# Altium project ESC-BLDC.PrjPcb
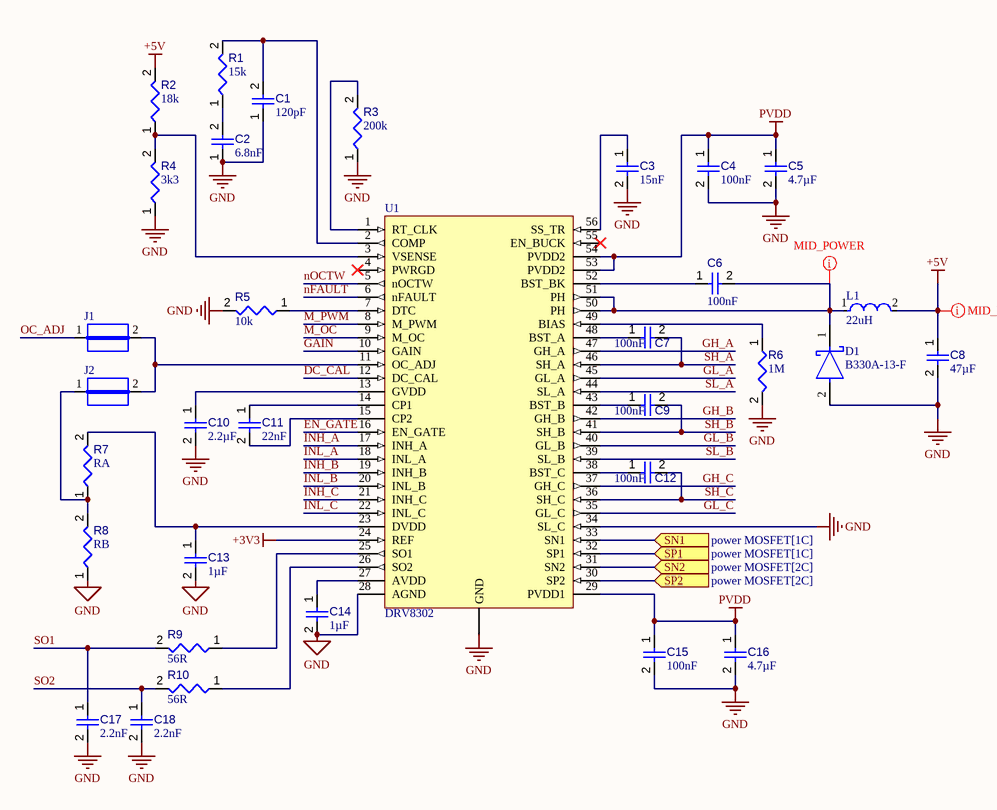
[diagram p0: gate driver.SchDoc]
5 sheets, 131 parts. Net scope: global (net labels, ports and power ports of the same name join across sheets).
Board file: BLDC_ESC.PcbDoc
Sheets:
  gate driver.SchDoc
  power MOSFET.SchDoc
  rotor angle sensor.SchDoc
  CAN.SchDoc
  main controller.SchDoc

## Sheet gate driver.SchDoc
size A4; SheetNumber: 1; SheetTotal: 5

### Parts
C1  value 120pF  [CAPC1005X56X25NL10T15]  (hidden comment: Capacitor 6.8 nF +/- 10% 16 V 0402)
C2  value 6.8nF  [CAPC1005X56X25NL10T15]  (hidden comment: Capacitor 6.8 nF +/- 10% 16 V 0402)
C3  value 15nF  [CAPC0402(1005)60_L]  (hidden comment: Capacitor 22nF +/-20% 10V 0402)
C4  value 100nF  [CAPC1608X90X40NL10T20]  (hidden comment: Capacitor 100 nF +/-10% 50 V 0603)
C5  value 4.7µF  [CAPC0603(1608)100_L]  (hidden comment: Capacitor 4.7µF +/-20% 10V 0603)
C6  value 100nF  [CAPC1608X90X40NL10T20]  (hidden comment: Capacitor 100 nF +/-10% 50 V 0603)
C7  value 100nF  [CAPC1608X90X40NL10T20]  (hidden comment: Capacitor 100 nF +/-10% 50 V 0603)
C8  value 47µF  [CAPC0805(2012)145_L]  (hidden comment: Capacitor 47µF +/-40% 6.3V 0805)
C9  value 100nF  [CAPC1608X90X40NL10T20]  (hidden comment: Capacitor 100 nF +/-10% 50 V 0603)
C10  value 2.2µF  [CAPC0402(1005)60_L]  (hidden comment: Capacitor 2,2µF +/-20% 10V 0402)
C11  value 22nF  [CAPC0402(1005)60_L]  (hidden comment: Capacitor 22nF +/-20% 10V 0402)
C12  value 100nF  [CAPC1608X90X40NL10T20]  (hidden comment: Capacitor 100 nF +/-10% 50 V 0603)
C13  value 1µF  [CAPC0402(1005)60_L]  (hidden comment: Capacitor 1µF +/-20% 10V 0402)
C14  value 1µF  [CAPC0402(1005)60_L]  (hidden comment: Capacitor 1µF +/-20% 10V 0402)
C15  value 100nF  [CAPC1608X90X40NL10T20]  (hidden comment: Capacitor 100 nF +/-10% 50 V 0603)
C16  value 4.7µF  [CAPC0603(1608)100_L]  (hidden comment: Capacitor 4.7µF +/-20% 10V 0603)
C17  value 2.2nF  [CAPC0402(1005)60_L]  (hidden comment: Capacitor 22nF +/-20% 10V 0402)
C18  value 2.2nF  [CAPC0402(1005)60_L]  (hidden comment: Capacitor 22nF +/-20% 10V 0402)
D1  B330A-13-F  [FP-SMA-MFG]
J1  JUMPER  [JUMPER]  (value not drawn)
J2  JUMPER  [JUMPER]  (value not drawn)
L1  22uH  [FP-IHLP-2525CZ-FP_2_413x3-MFG]
R1  value 15k  [RESC1005X40X25ML10T10]  (hidden comment: Resistor 15k +/-1% 0402 63 mW)
R2  value 18k  [RESC1608X55X25ML10T15]  (hidden comment: Resistor 10k +/-1% 0603 100 mW)
R3  value 200k  [RESC0402(1005)_L]  (hidden comment: Resistor 200K +/-1 % 0402 63 mW)
R4  value 3k3  [RESC1608X55X25ML10T15]  (hidden comment: Resistor 10k +/-1% 0603 100 mW)
R5  value 10k  [RESC1005X40X25ML05T05]  (hidden comment: Resistor 10k +/-1% 0402 100 mW)
R6  value 1M  [RESC1608X55X25ML10T15]  (hidden comment: Resistor 10k +/-1% 0603 100 mW)
R7  value RA  [RESC1608X55X25ML10T15]  (hidden comment: Resistor 10k +/-1% 0603 100 mW)
R8  value RB  [RESC1608X55X25ML10T15]  (hidden comment: Resistor 10k +/-1% 0603 100 mW)
R9  value 56R  [RESC1005X40X25ML05T05]  (hidden comment: Resistor 10k +/-1% 0402 100 mW)
R10  value 56R  [RESC1005X40X25ML05T05]  (hidden comment: Resistor 10k +/-1% 0402 100 mW)
U1  DRV8302  [HTSSOP-56]

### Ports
SN1 (in, see power MOSFET[1C]), SN2 (in, see power MOSFET[2C]), SP1 (in, see power MOSFET[1C]), SP2 (in, see power MOSFET[2C])

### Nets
+3V3: U1.24(REF)
+5V: C8.1 L1.2 R2.2
GND: C1.1 C2.1 C3.2 C4.2 C5.2 C8.2 C10.2 C13.2 C14.2 C15.2 C16.2 C17.2 C18.2 D1.2(A) R3.1 R4.1 R5.2 R6.2 R8.1 U1.28(AGND) U1.30(SP2) U1.32(SP1) U1.34(SL_C) U1.EXP(GND) ; port SP1, port SP2
PVDD: C4.1 C5.1 C15.1 C16.1 U1.29(PVDD1) U1.53(PVDD2) U1.54(PVDD2)
DC_CAL: U1.12(DC_CAL)
EN_GATE: U1.16(EN_GATE)
GAIN: U1.10(GAIN)
GH_A: U1.47(GH_A)
GH_B: U1.42(GH_B)
GH_C: U1.37(GH_C)
GL_A: U1.45(GL_A)
GL_B: U1.40(GL_B)
GL_C: U1.35(GL_C)
INH_A: U1.17(INH_A)
INH_B: U1.19(INH_B)
INH_C: U1.21(INH_C)
INL_A: U1.18(INL_A)
INL_B: U1.20(INL_B)
INL_C: U1.22(INL_C)
M_OC: U1.9(M_OC)
M_PWM: U1.8(M_PWM)
nFAULT: U1.6(nFAULT)
nOCTW: U1.5(nOCTW)
OC_ADJ: J1.1
SH_A: C7.2 U1.46(SH_A)
SH_B: C9.2 U1.41(SH_B)
SH_C: C12.2 U1.36(SH_C)
SL_A: U1.33(SN1) U1.44(SL_A) ; port SN1
SL_B: U1.31(SN2) U1.39(SL_B) ; port SN2
SO1: C17.1 R9.2
SO2: C18.1 R10.2
NetC1_2: C1.2 R1.2 U1.2(COMP)
NetC2_2: C2.2 R1.1
NetC3_1: C3.1 U1.56(SS_TR)
NetC6_1: C6.1 U1.52(BST_BK)
NetC6_2: C6.2 D1.1(C) L1.1 U1.50(PH) U1.51(PH)
NetC7_1: C7.1 U1.48(BST_A)
NetC9_1: C9.1 U1.43(BST_B)
NetC10_1: C10.1 U1.13(GVDD)
NetC11_1: C11.1 U1.14(CP1)
NetC11_2: C11.2 U1.15(CP2)
NetC12_1: C12.1 U1.38(BST_C)
NetC13_1: C13.1 R7.2 U1.23(DVDD)
NetC14_1: C14.1 U1.27(AVDD)
NetJ1_2: J1.2 J2.2 U1.11(OC_ADJ)
NetJ2_1: J2.1 R7.1 R8.2
NetR2_1: R2.1 R4.2 U1.3(VSENSE)
NetR3_2: R3.2 U1.1(RT_CLK)
NetR5_1: R5.1 U1.7(DTC)
NetR6_1: R6.1 U1.49(BIAS)
NetR9_1: R9.1 U1.25(SO1)
NetR10_1: R10.1 U1.26(SO2)

Not connected (* = marked no-connect by the designer): U1 4(PWRGD)* 55(EN_BUCK)*

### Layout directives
net class MID_POWER: +5V, NetC6_2

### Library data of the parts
C1 C2 = CMP-001-00000-6: Chip Capacitor, 6.8 nF, +/- 10%, 16 V, 0402 (1005 Metric); Capacitor Type: Ceramic; Voltage Rating: 16V
C3 C11 C17 C18 = CMP-001-00062-3: Chip Capacitor, 22nF +/-20%, 10V, 0402, Thickness 0.6 mm; Tolerance: 10%
C4 C6 C7 C9 C12 C15 = CMP-001-00017-6: Chip Capacitor, 100 nF, +/- 10%, 50 V, 0603 (1608 Metric); Voltage Rating: 50V; Capacitor Type: Ceramic
C5 C16 = CMP-001-00076-4: Chip Capacitor, 4.7µF +/-20%, 10V, 0603, Thickness 1 mm; Tolerance: 10%
C8 = CMP-001-00082-4: Chip Capacitor, 47µF +/-40%, 6.3V, 0805, Thickness 1.45 mm; Tolerance: 10%
C10 = CMP-001-00056-4: Chip Capacitor, 2,2µF +/-20%, 10V, 0402, Thickness 0.6 mm; Tolerance: 10%
C13 C14 = CMP-001-00063-3: Chip Capacitor, 1µF +/-20%, 10V, 0402, Thickness 0.6 mm; Tolerance: 10%
D1 = CMP-2000-05896-2: DIODE SCHOTTKY 30V 3A SMA; Manufacturer: Diodes; Max Junction Temp: +150°C; Standoff Height: 0.05mm; Peak Reverse Current: 0.5mA; Capacitance: 200pF; Value: 200pF; Description: Diode Schottky 30V 3A Surface Mount SMA; Max Surge Forward Current: 80A; Automotive Grade: Grade 0
J1 J2 = CMP-009-00061-2
L1 = CMP-2000-06442-2: Commercial Inductors, Low DCR Series 22uH 2.9A 135mΩ 20%; Self Resonant Frequency: 1MHz; Shielding: Shielded; Core Material: Ferrite; DC Resistance (DCR): 135mR; Test Frequency: 100kHz; Saturation Current: 2.5A
R1 = CMP-009-00026-5: Chip Resistor, 15 KOhm, +/- 1%, 0.063 W, -55 to 155 degC, 0402 (1005 Metric); Power: 63mW
R2 R4 R6-R8 = CMP-009-00017-5: Chip Resistor, 10 KOhm, +/- 1%, 01 W, -55 to 155 degC, 0603 (1608 Metric); Voltage Rating: 50V; Power: 100mW
R3 = CMP-009-00163-3: Chip Resistor, 200 kOhms, +/-1 %, 63 mW, -55 to 155 degC, 0402; Power: 63mW; Tolerance: 1%
R5 R9 R10 = CMP-009-00015-5: Chip Resistor, 10 KOhm, +/- 1%, 0.1 W, -55 to 155 degC, 0402 (1005 Metric); Voltage Rating: 50V; Power: 100mW
U1 = DRV8302: Three phases gate driver with dual current shunt amplifiers and buck regulator

## Sheet power MOSFET.SchDoc
size A4; SheetNumber: 2; SheetTotal: 5
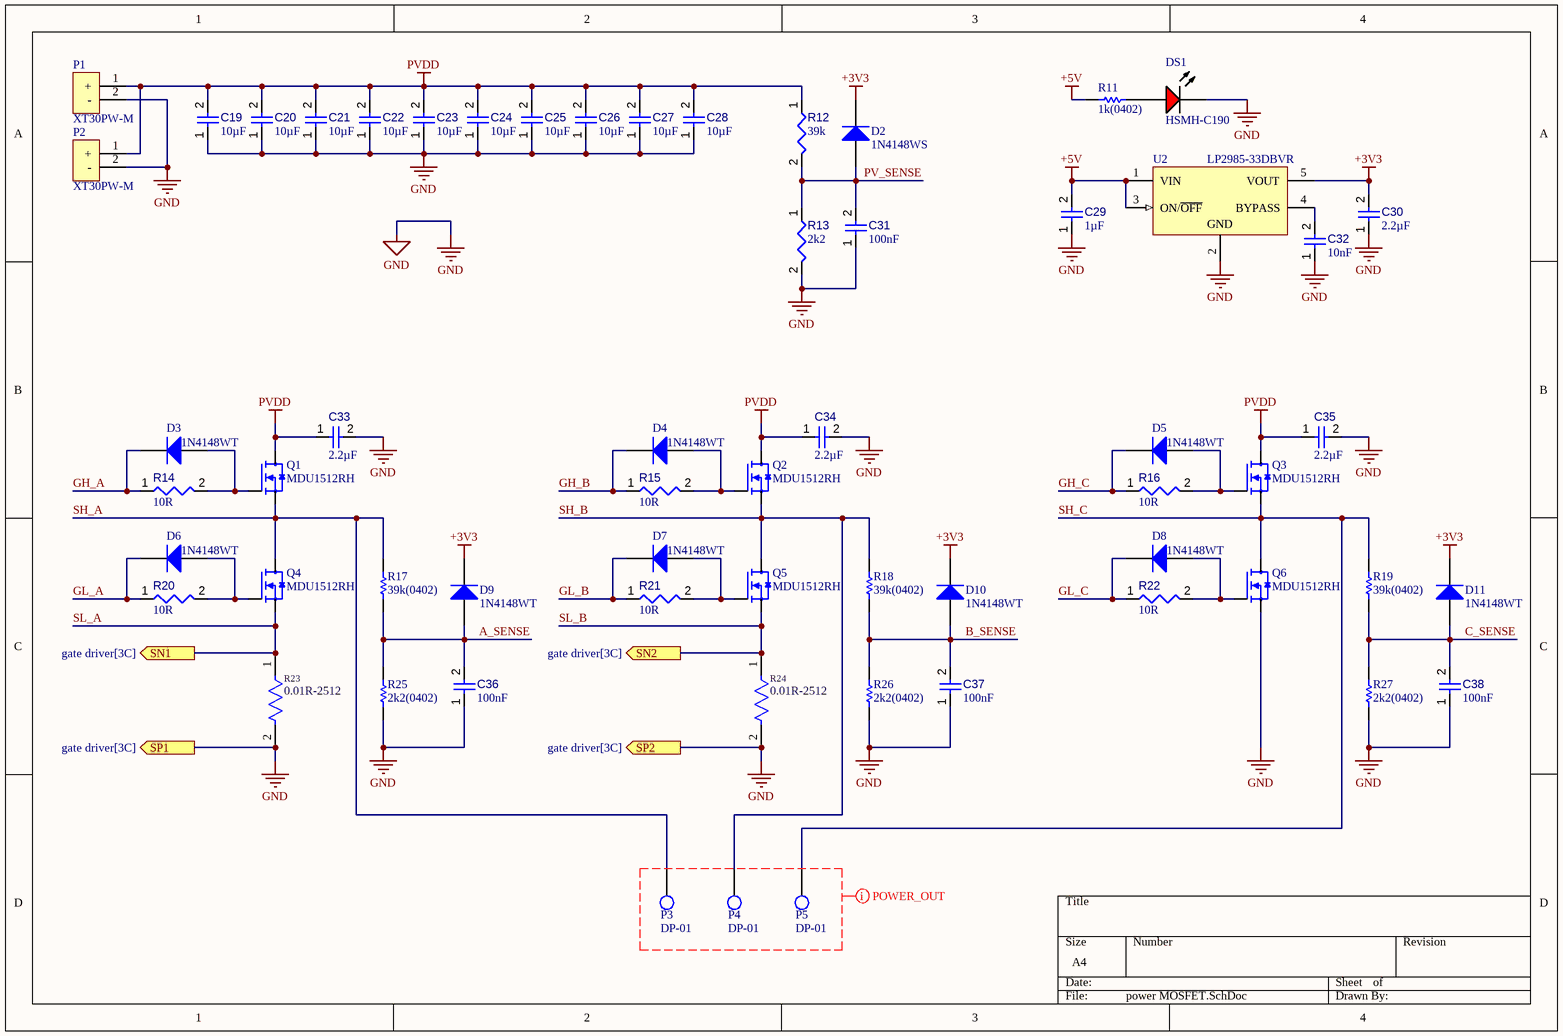
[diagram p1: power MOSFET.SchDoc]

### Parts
C19  value 10µF  [CAPC2013X135X45NL10T25]  (hidden comment: Capacitor 10 uF +/- 10% 16 V 0805)
C20  value 10µF  [CAPC2013X135X45NL10T25]  (hidden comment: Capacitor 10 uF +/- 10% 16 V 0805)
C21  value 10µF  [CAPC2013X135X45NL10T25]  (hidden comment: Capacitor 10 uF +/- 10% 16 V 0805)
C22  value 10µF  [CAPC2013X135X45NL10T25]  (hidden comment: Capacitor 10 uF +/- 10% 16 V 0805)
C23  value 10µF  [CAPC2013X135X45NL10T25]  (hidden comment: Capacitor 10 uF +/- 10% 16 V 0805)
C24  value 10µF  [CAPC2013X135X45NL10T25]  (hidden comment: Capacitor 10 uF +/- 10% 16 V 0805)
C25  value 10µF  [CAPC2013X135X45NL10T25]  (hidden comment: Capacitor 10 uF +/- 10% 16 V 0805)
C26  value 10µF  [CAPC2013X135X45NL10T25]  (hidden comment: Capacitor 10 uF +/- 10% 16 V 0805)
C27  value 10µF  [CAPC2013X135X45NL10T25]  (hidden comment: Capacitor 10 uF +/- 10% 16 V 0805)
C28  value 10µF  [CAPC2013X135X45NL10T25]  (hidden comment: Capacitor 10 uF +/- 10% 16 V 0805)
C29  value 1µF  [CAPC1608X90X35ML15T15]  (hidden comment: Capacitor 1uF +/- 10% 16V 0603)
C30  value 2.2µF  [CAPC1608X90X35ML15T15]  (hidden comment: Capacitor 1uF +/- 10% 16V 0603)
C31  value 100nF  [CAPC0402(1005)60_L]  (hidden comment: Capacitor 100nF +/-20% 50V 0402)
C32  value 10nF  [CAPC0402(1005)60_L]  (hidden comment: Capacitor 10nF +/-20% 50V 0402)
C33  value 2.2µF  [CAPC0603(1608)100_L]  (hidden comment: Capacitor 4.7µF +/-20% 10V 0603)
C34  value 2.2µF  [CAPC0603(1608)100_L]  (hidden comment: Capacitor 4.7µF +/-20% 10V 0603)
C35  value 2.2µF  [CAPC0603(1608)100_L]  (hidden comment: Capacitor 4.7µF +/-20% 10V 0603)
C36  value 100nF  [CAPC0402(1005)60_L]  (hidden comment: Capacitor 100nF +/-20% 50V 0402)
C37  value 100nF  [CAPC0402(1005)60_L]  (hidden comment: Capacitor 100nF +/-20% 50V 0402)
C38  value 100nF  [CAPC0402(1005)60_L]  (hidden comment: Capacitor 100nF +/-20% 50V 0402)
D2  1N4148WS  [FAIR-SOD-323_V]
D3  1N4148WT  [FAIR-SOD-523F-2_V]
D4  1N4148WT  [FAIR-SOD-523F-2_V]
D5  1N4148WT  [FAIR-SOD-523F-2_V]
D6  1N4148WT  [FAIR-SOD-523F-2_V]
D7  1N4148WT  [FAIR-SOD-523F-2_V]
D8  1N4148WT  [FAIR-SOD-523F-2_V]
D9  1N4148WT  [FAIR-SOD-523F-2_V]
D10  1N4148WT  [FAIR-SOD-523F-2_V]
D11  1N4148WT  [FAIR-SOD-523F-2_V]
DS1  HSMH-C190  [AVAG-HSMX-C190_V]
P1  XT30PW-M  [XT30PW-M]
P2  XT30PW-M  [XT30PW-M]
P3  DP-01  [DP-01]
P4  DP-01  [DP-01]
P5  DP-01  [DP-01]
Q1  MDU1512RH  [PDFN56]
Q2  MDU1512RH  [PDFN56]
Q3  MDU1512RH  [PDFN56]
Q4  MDU1512RH  [PDFN56]
Q5  MDU1512RH  [PDFN56]
Q6  MDU1512RH  [PDFN56]
R11  value 1k(0402)  [RESC1005X40X25ML05T05]  (hidden comment: Resistor 0R +/- 5% 0402 100 mW)
R12  value 39k  [RESC1608X55X25ML10T15]  (hidden comment: Resistor 10k +/-1% 0603 100 mW)
R13  value 2k2  [RESC1608X55X25ML10T15]  (hidden comment: Resistor 10k +/-1% 0603 100 mW)
R14  value 10R  [RESC0603(1608)_L]  (hidden comment: Resistor 120R +/-5 % 0603 0.1 W)
R15  value 10R  [RESC0603(1608)_L]  (hidden comment: Resistor 120R +/-5 % 0603 0.1 W)
R16  value 10R  [RESC0603(1608)_L]  (hidden comment: Resistor 120R +/-5 % 0603 0.1 W)
R17  value 39k(0402)  [RESC1005X40X25ML05T05]  (hidden comment: Resistor 0R +/- 5% 0402 100 mW)
R18  value 39k(0402)  [RESC1005X40X25ML05T05]  (hidden comment: Resistor 0R +/- 5% 0402 100 mW)
R19  value 39k(0402)  [RESC1005X40X25ML05T05]  (hidden comment: Resistor 0R +/- 5% 0402 100 mW)
R20  value 10R  [RESC0603(1608)_L]  (hidden comment: Resistor 120R +/-5 % 0603 0.1 W)
R21  value 10R  [RESC0603(1608)_L]  (hidden comment: Resistor 120R +/-5 % 0603 0.1 W)
R22  value 10R  [RESC0603(1608)_L]  (hidden comment: Resistor 120R +/-5 % 0603 0.1 W)
R23  0.01R-2512  [FP-CRCW2512-e3-MFG]
R24  0.01R-2512  [FP-CRCW2512-e3-MFG]
R25  value 2k2(0402)  [RESC1005X40X25ML05T05]  (hidden comment: Resistor 0R +/- 5% 0402 100 mW)
R26  value 2k2(0402)  [RESC1005X40X25ML05T05]  (hidden comment: Resistor 0R +/- 5% 0402 100 mW)
R27  value 2k2(0402)  [RESC1005X40X25ML05T05]  (hidden comment: Resistor 0R +/- 5% 0402 100 mW)
U2  LP2985-33DBVR  [TI-DBV5_V]

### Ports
SN1 (out, see gate driver[3C]), SN2 (out, see gate driver[3C]), SP1 (out, see gate driver[3C]), SP2 (out, see gate driver[3C])

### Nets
+3V3: C30.2 D2.2(K) D9.1(K) D10.1(K) D11.1(K) U2.5(VOUT)
+5V: C29.2 R11.1 U2.1(VIN) U2.3(ON/~{OFF})
GND: C19.1 C20.1 C21.1 C22.1 C23.1 C24.1 C25.1 C26.1 C27.1 C28.1 C29.1 C30.1 C31.1 C32.1 C33.2 C34.2 C35.2 C36.1 C37.1 C38.1 DS1.2(K) P1.2(-) P2.2(-) Q6.1(S) R13.2 R23.2 R24.2 R25.1 R26.1 R27.1 U2.2(GND) ; port SP1, port SP2
PVDD: C19.2 C20.2 C21.2 C22.2 C23.2 C24.2 C25.2 C26.2 C27.2 C28.2 C33.1 C34.1 C35.1 P1.1(+) P2.1(+) Q1.EXT(D) Q2.EXT(D) Q3.EXT(D) R12.1
A_SENSE: C36.2 D9.2(A) R17.1 R25.2
B_SENSE: C37.2 D10.2(A) R18.1 R26.2
C_SENSE: C38.2 D11.2(A) R19.1 R27.2
GH_A: D3.1(K) R14.1
GH_B: D4.1(K) R15.1
GH_C: D5.1(K) R16.1
GL_A: D6.1(K) R20.1
GL_B: D7.1(K) R21.1
GL_C: D8.1(K) R22.1
PV_SENSE: C31.2 D2.1(A) R12.2 R13.1
SH_A: P3.X Q1.1(S) Q4.EXT(D) R17.2
SH_B: P4.X Q2.1(S) Q5.EXT(D) R18.2
SH_C: P5.X Q3.1(S) Q6.EXT(D) R19.2
SL_A: Q4.1(S) R23.1 ; port SN1
SL_B: Q5.1(S) R24.1 ; port SN2
NetC32_2: C32.2 U2.4(BYPASS)
NetD3_2: D3.2(A) Q1.4(G) R14.2
NetD4_2: D4.2(A) Q2.4(G) R15.2
NetD5_2: D5.2(A) Q3.4(G) R16.2
NetD6_2: D6.2(A) Q4.4(G) R20.2
NetD7_2: D7.2(A) Q5.4(G) R21.2
NetD8_2: D8.2(A) Q6.4(G) R22.2
NetDS1_1: DS1.1(A) R11.2

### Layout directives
net class POWER_OUT: (no net found under the mark)

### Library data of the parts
C19-C28 = CMP-001-00015-6: Chip Capacitor, 10 uF, +/- 10%, 16 V, 0805 (2012 Metric); Voltage Rating: 16V; Capacitor Type: Ceramic
C29 C30 = CMP-001-00004-6: Chip Capacitor, 1 uF, +/- 10%, 16 V, 0603 (1608 Metric); Capacitor Type: Ceramic
C31 C36-C38 = CMP-001-00067-3: Chip Capacitor, 100nF +/-20%, 50V, 0402, Thickness 0.6 mm; Tolerance: 10%
C32 = CMP-001-00069-3: Chip Capacitor, 10nF +/-20%, 50V, 0402, Thickness 0.6 mm; Tolerance: 5%
C33-C35 = CMP-001-00076-4: as C5 on sheet gate driver
D2 = CMP-004-00001-2: Small Signal Diode, 75 V, 0.15 A, -55 to 150 degC, 2-Pin SOD-323, RoHS, Tape and Reel; Manufacturer: Fairchild; Recovery Time: 4ns; Forward Voltage: 1V; Peak Reverse Current: 5uA; Forward Current: 150mA; Capacitance: -323f
D3-D11 = CMP-0881-00001-1: High Conductance Fast Switching Diode, 75 V, -55 to 150 degC, 2-Pin SOD523F, RoHS; Manufacturer: Fairchild Semiconductor; IR (VR: 75 V)=5 uA Max.; VF: 1 V Max.; BVR (IR: 5 uA)=75 V Min.; CO: 4 pF Max.
DS1 = CMP-007-00014-2: LED Uni-Color Red, 65 mW, 20 mA, -40 to 85 degC, 2-Pin SMD, RoHS, Tape and Reel; Manufacturer: Avago; Nominal Vf: 1.8V; Luminous Intensity: 17mcd; Power: 78mW; Forward Current: 20mA; Lens Style: Diffused; Viewing Angle: 170degrees
Q1-Q6 = MDU1512RH: pin to pad: 1>1+2+3 EXT>5+6+7+8+EXT
R11 R17-R19 R25-R27 = CMP-009-00005-5: Chip Resistor, 0 Ohm, 0.1 W, -55 to 155 degC, 0402 (1005 Metric); Power: 100mW; Voltage Rating: 50V
R12 R13 = CMP-009-00017-5: as R2 on sheet gate driver
R14-R16 R20-R22 = CMP-009-00176-3: Chip Resistor, 120 Ohms, +/-5 %, 0.1 W, -55 to 155 degC, 0603; Power: 100mW; Tolerance: 5%
R23 R24 = CMP-02407-004199-1: RES Thick Film, 100kΩ, 1%, 1W, 100ppm/°C, 2512; Voltage Rating: 500V; Resistance: 100kR
U2 = CMP-019-00026-3: Single Output Low Noise LDO, 150 mA, Fixed 3.3 V Output, 1.5% Tolerance, 2.2 to 16 V Input, Low IQ, 5-Pin SOT-23 (DBV), -40 to 125 degC, Green (RoHS & no Sb/Br), Tape and Reel; Manufacturer: Texas Instruments; Output Current: 150mA; Package Version: 4073253-4/N, 12/2014; Outputs: 1; Dropout Voltage: 3mV; Output Voltage: 3.3V; Max Input Voltage: 16V; Min Input Voltage: 2.2V

## Sheet rotor angle sensor.SchDoc
size A4; SheetNumber: 3; SheetTotal: 5
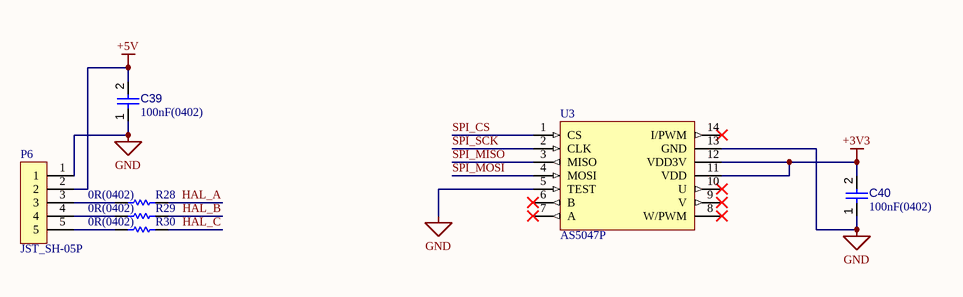
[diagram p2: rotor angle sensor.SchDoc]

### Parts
C39  value 100nF(0402)  [CAPC0402(1005)60_L]  (hidden comment: Capacitor 100nF +/-20% 50V 0402)
C40  value 100nF(0402)  [CAPC0402(1005)60_L]  (hidden comment: Capacitor 100nF +/-20% 50V 0402)
P6  JST_SH-05P  [SH-5P-SIDE]
R28  value 0R(0402)  [RESC1005X40X25ML05T05]  (hidden comment: Resistor 0R +/- 5% 0402 100 mW)
R29  value 0R(0402)  [RESC1005X40X25ML05T05]  (hidden comment: Resistor 0R +/- 5% 0402 100 mW)
R30  value 0R(0402)  [RESC1005X40X25ML05T05]  (hidden comment: Resistor 0R +/- 5% 0402 100 mW)
U3  AS5047P  [TSSOP-14]

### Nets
+3V3: C40.2 U3.11(VDD) U3.12(VDD3V)
+5V: C39.2 P6.2
GND: C39.1 C40.1 P6.1 U3.5(TEST) U3.13(GND)
HAL_A: R28.2
HAL_B: R29.2
HAL_C: R30.2
SPI_CS: U3.1(CS)
SPI_MISO: U3.3(MISO)
SPI_MOSI: U3.4(MOSI)
SPI_SCK: U3.2(CLK)
NetP6_3: P6.3 R28.1
NetP6_4: P6.4 R29.1
NetP6_5: P6.5 R30.1

Not connected (* = marked no-connect by the designer): U3 6(B)* 7(A)* 8(W/PWM)* 9(V)* 10(U)* 14(I/PWM)*

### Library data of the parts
C39 C40 = CMP-001-00067-3: as C31 on sheet power MOSFET
R28-R30 = CMP-009-00005-5: as R11 on sheet power MOSFET

## Sheet CAN.SchDoc
size A4; SheetNumber: 4; SheetTotal: 5
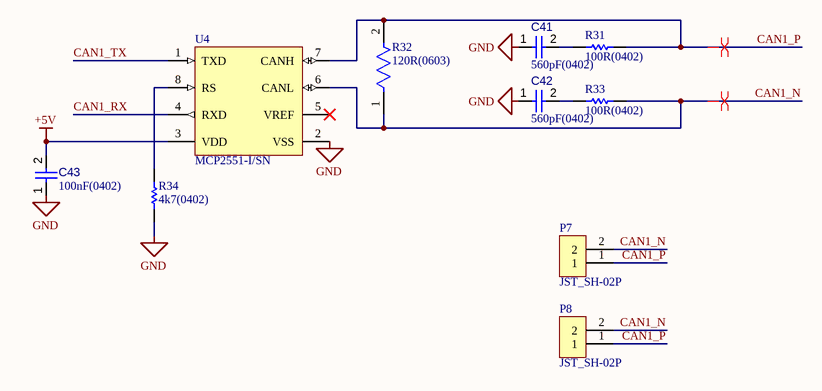
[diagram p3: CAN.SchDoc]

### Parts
C41  value 560pF(0402)  [CAPC0402(1005)60_L]  (hidden comment: Capacitor 100nF +/-20% 50V 0402)
C42  value 560pF(0402)  [CAPC0402(1005)60_L]  (hidden comment: Capacitor 100nF +/-20% 50V 0402)
C43  value 100nF(0402)  [CAPC0402(1005)60_L]  (hidden comment: Capacitor 100nF +/-20% 50V 0402)
P7  JST_SH-02P  [SH-2P-SIDE]
P8  JST_SH-02P  [SH-2P-SIDE]
R31  value 100R(0402)  [RESC1005X40X25ML05T05]  (hidden comment: Resistor 0R +/- 5% 0402 100 mW)
R32  120R(0603)  [FP-RMCF0603-IPC_A]
R33  value 100R(0402)  [RESC1005X40X25ML05T05]  (hidden comment: Resistor 0R +/- 5% 0402 100 mW)
R34  value 4k7(0402)  [RESC1005X40X25ML05T05]  (hidden comment: Resistor 0R +/- 5% 0402 100 mW)
U4  MCP2551-I/SN  [MCHP-SN8_V]

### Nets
+5V: C43.2 U4.3(VDD)
GND: C41.1 C42.1 C43.1 R34.1 U4.2(VSS)
CAN1_N: P7.2 P8.2 R32.1 R33.1 U4.6(CANL)
CAN1_P: P7.1 P8.1 R31.1 R32.2 U4.7(CANH)
CAN1_RX: U4.4(RXD)
CAN1_TX: U4.1(TXD)
NetC41_2: C41.2 R31.2
NetC42_2: C42.2 R33.2
NetR34_2: R34.2 U4.8(RS)

Not connected (* = marked no-connect by the designer): U4 5(VREF)*

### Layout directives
differential pair: CAN1_N, CAN1_P

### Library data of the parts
C41-C43 = CMP-001-00067-3: as C31 on sheet power MOSFET
R31 R33 R34 = CMP-009-00005-5: as R11 on sheet power MOSFET
R32 = CMP-26527-001340-1: 120Ω ±5% 0.1W 0603 Thick Film Chip Resistor AEC-Q200 compliant; Power Rating: 100mW; Temperature Coefficient: 100ppm/°C
U4 = CMP-0186-00138-3: High-Speed CAN Transceiver, / 1 Mb/s, 4.5 to 5.5 V, 8-Pin SOIC (SN), Industrial Temperature, RoHS, Tube; Manufacturer: Microchip

## Sheet main controller.SchDoc
size A4; SheetNumber: 5; SheetTotal: 5
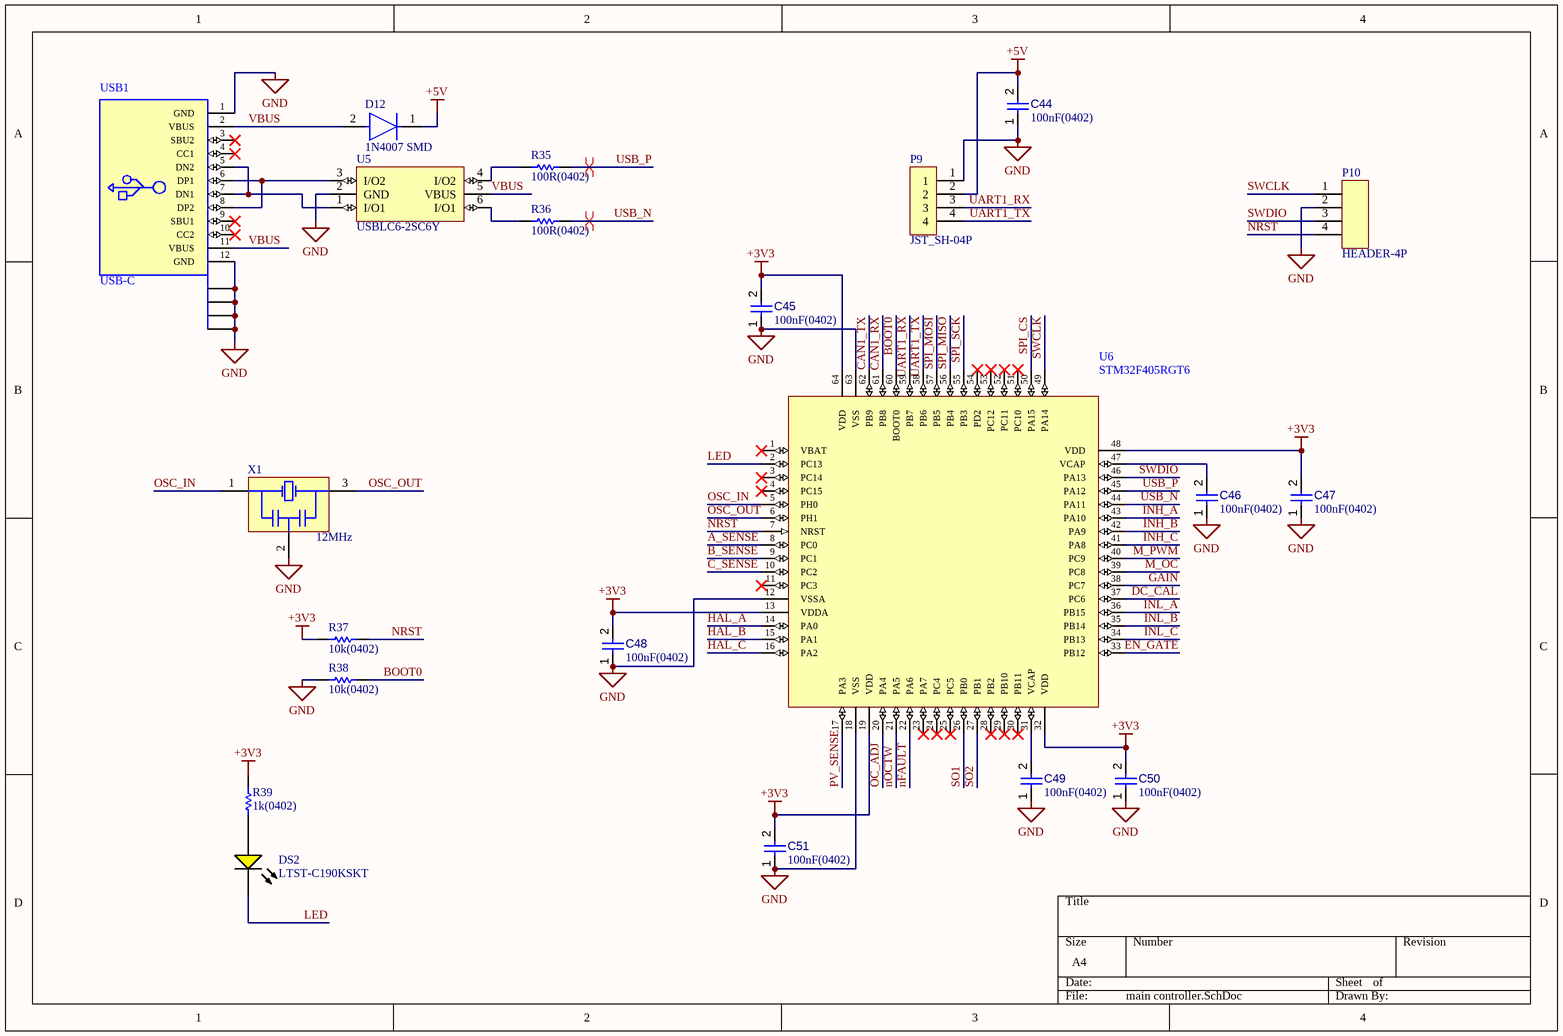
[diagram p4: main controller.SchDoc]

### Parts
C44  value 100nF(0402)  [CAPC0402(1005)60_L]  (hidden comment: Capacitor 100nF +/-20% 50V 0402)
C45  value 100nF(0402)  [CAPC0402(1005)60_L]  (hidden comment: Capacitor 100nF +/-20% 50V 0402)
C46  value 100nF(0402)  [CAPC0402(1005)60_L]  (hidden comment: Capacitor 100nF +/-20% 50V 0402)
C47  value 100nF(0402)  [CAPC0402(1005)60_L]  (hidden comment: Capacitor 100nF +/-20% 50V 0402)
C48  value 100nF(0402)  [CAPC0402(1005)60_L]  (hidden comment: Capacitor 100nF +/-20% 50V 0402)
C49  value 100nF(0402)  [CAPC0402(1005)60_L]  (hidden comment: Capacitor 100nF +/-20% 50V 0402)
C50  value 100nF(0402)  [CAPC0402(1005)60_L]  (hidden comment: Capacitor 100nF +/-20% 50V 0402)
C51  value 100nF(0402)  [CAPC0402(1005)60_L]  (hidden comment: Capacitor 100nF +/-20% 50V 0402)
D12  1N4007 SMD  [FP-1N4007_SMD-IPC_A]
DS2  LTST-C190KSKT  [LTST-C190KSKT_V]
P9  JST_SH-04P  [SH-04-SIDE]
P10  HEADER-4P  [female_header-4p]
R35  value 100R(0402)  [RESC1005X40X25ML05T05]  (hidden comment: Resistor 0R +/- 5% 0402 100 mW)
R36  value 100R(0402)  [RESC1005X40X25ML05T05]  (hidden comment: Resistor 0R +/- 5% 0402 100 mW)
R37  value 10k(0402)  [RESC1005X40X25ML05T05]  (hidden comment: Resistor 0R +/- 5% 0402 100 mW)
R38  value 10k(0402)  [RESC1005X40X25ML05T05]  (hidden comment: Resistor 0R +/- 5% 0402 100 mW)
R39  value 1k(0402)  [RESC1005X40X25ML05T05]  (hidden comment: Resistor 0R +/- 5% 0402 100 mW)
U5  USBLC6-2SC6Y  [SOT23-6]
U6  STM32F405RGT6  [QFP50P1200X1200X160-64N]
USB1  USB-C  [USB-C-A40-00119]
X1  12MHz  [MURA-CSTCE_G_V]

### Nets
+3V3: C45.2 C47.2 C48.2 C50.2 C51.2 R37.1 R39.1 U6.13(VDDA) U6.19(VDD) U6.32(VDD) U6.48(VDD) U6.64(VDD)
+5V: C44.2 D12.1(C) P9.2
GND: C44.1 C45.1 C46.1 C47.1 C48.1 C49.1 C50.1 C51.1 P9.1 P10.2 R38.2 U5.2(GND) U6.12(VSSA) U6.18(VSS) U6.63(VSS) USB1.1(GND) USB1.12(GND) USB1.A(EXT) USB1.B(EXT1) USB1.C(EXT2) USB1.D(EXT3) X1.2(GND)
A_SENSE: U6.8(PC0)
B_SENSE: U6.9(PC1)
BOOT0: R38.1 U6.60(BOOT0)
C_SENSE: U6.10(PC2)
CAN1_RX: U6.61(PB8)
CAN1_TX: U6.62(PB9)
DC_CAL: U6.37(PC6)
EN_GATE: U6.33(PB12)
GAIN: U6.38(PC7)
HAL_A: U6.14(PA0)
HAL_B: U6.15(PA1)
HAL_C: U6.16(PA2)
INH_A: U6.43(PA10)
INH_B: U6.42(PA9)
INH_C: U6.41(PA8)
INL_A: U6.36(PB15)
INL_B: U6.35(PB14)
INL_C: U6.34(PB13)
LED: DS2.2(K) U6.2(PC13)
M_OC: U6.39(PC8)
M_PWM: U6.40(PC9)
nFAULT: U6.22(PA6)
nOCTW: U6.21(PA5)
NRST: P10.4 R37.2 U6.7(NRST)
OC_ADJ: U6.20(PA4)
OSC_IN: U6.5(PH0) X1.1(X1)
OSC_OUT: U6.6(PH1) X1.3(X2)
PV_SENSE: U6.17(PA3)
SO1: U6.26(PB0)
SO2: U6.27(PB1)
SPI_CS: U6.50(PA15)
SPI_MISO: U6.56(PB4)
SPI_MOSI: U6.57(PB5)
SPI_SCK: U6.55(PB3)
SWCLK: P10.1 U6.49(PA14)
SWDIO: P10.3 U6.46(PA13)
UART1_RX: P9.3 U6.59(PB7)
UART1_TX: P9.4 U6.58(PB6)
USB_N: R36.1 U6.44(PA11)
USB_P: R35.1 U6.45(PA12)
VBUS: D12.2(A) U5.5(VBUS) USB1.2(VBUS) USB1.11(VBUS)
NetC46_2: C46.2 U6.47(VCAP)
NetC49_2: C49.2 U6.31(VCAP)
NetDS2_1: DS2.1(A) R39.2
NetR35_2: R35.2 U5.4(I/O2)
NetR36_2: R36.2 U5.6(I/O1)
NetU5_1: U5.1(I/O1) USB1.5(DN2) USB1.7(DN1)
NetU5_3: U5.3(I/O2) USB1.6(DP1) USB1.8(DP2)

Not connected (* = marked no-connect by the designer): U6 1(VBAT)* 3(PC14)* 4(PC15)* 11(PC3)* 23(PA7)* 24(PC4)* 25(PC5)* 28(PB2)* 29(PB10)* 30(PB11)* 51(PC10)* 52(PC11)* 53(PC12)* 54(PD2)*; USB1 3(SBU2)* 4(CC1)* 9(SBU1)* 10(CC2)*

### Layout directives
differential pair: USB_N, USB_P

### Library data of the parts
C44-C51 = CMP-001-00067-3: as C31 on sheet power MOSFET
D12 = CMP-12389-000001-1: Rectifier, 1Kv, 1A, Do-214Ac Rohs Compliant: Yes
DS2 = CMP-007-00025-2: LED Uni-Color Yellow, 75 mW, 30 mA, -30 to 85 degC, 2-Pin SMD, RoHS, Tape and Reel; Manufacturer: Lite-On; Lens Style: Diffused; Forward Current: 20mA; Nominal Vf: 2.1V; Forward Voltage: 2V; Luminous Intensity: 28mcd; Viewing Angle: 130degrees; Power: 75mW
R35-R39 = CMP-009-00005-5: as R11 on sheet power MOSFET
U5 = USBLC6-2SC6Y: Automotive very low capacitance ESD protection
U6 = STM32F405RGT6: MCU 32-Bit, ARM Cortex M4, 1MB Flash STMicroelectronics STM32F405RGT6, 32bit ARM Cortex M4F Microcontroller, 168MHz, 1024 kB Flash, 64-Pin LQFP   Source:  Datasheet; GateName_1: G$1; ALLIED_NUMBER: 70391099
USB1 = USB-C: GateName_1: G$1
X1 = CMP-2000-06123-1: Ceramic Resonator, 12 MHz, +/- 0.5%, -40 to 125 degC, 3-Pin SMD, RoHS, Tape and Reel; Manufacturer: Murata; Impedance: 30Ohm; Frequency Stability: ±0.2%; Catalog Drawings: CSTCE-(G,V)SeriesSide2 / CSTCE-(G,V)SeriesTop / CSTCE-(G,V)SeriesSide1 / CSTCE-(G,V)SeriesBottom; Dynamic Catalog: CERALOCK®,CSTCESeries; Other Names: 490-1220-6; Capacitance: 33pF

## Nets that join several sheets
+3V3: gate driver (U1.24), power MOSFET (6 pins), rotor angle sensor (C40.2 U3.11 U3.12), main controller (12 pins)
+5V: gate driver (C8.1 L1.2 R2.2), power MOSFET (C29.2 R11.1 U2.1 U2.3), rotor angle sensor (C39.2 P6.2), CAN (C43.2 U4.3), main controller (C44.2 D12.1 P9.2)
GND: gate driver (24 pins), power MOSFET (31 pins), rotor angle sensor (5 pins), CAN (5 pins), main controller (22 pins)
PVDD: gate driver (7 pins), power MOSFET (19 pins)
A_SENSE: power MOSFET (C36.2 D9.2 R17.1 R25.2), main controller (U6.8)
B_SENSE: power MOSFET (C37.2 D10.2 R18.1 R26.2), main controller (U6.9)
C_SENSE: power MOSFET (C38.2 D11.2 R19.1 R27.2), main controller (U6.10)
CAN1_RX: CAN (U4.4), main controller (U6.61)
CAN1_TX: CAN (U4.1), main controller (U6.62)
DC_CAL: gate driver (U1.12), main controller (U6.37)
EN_GATE: gate driver (U1.16), main controller (U6.33)
GAIN: gate driver (U1.10), main controller (U6.38)
GH_A: gate driver (U1.47), power MOSFET (D3.1 R14.1)
GH_B: gate driver (U1.42), power MOSFET (D4.1 R15.1)
GH_C: gate driver (U1.37), power MOSFET (D5.1 R16.1)
GL_A: gate driver (U1.45), power MOSFET (D6.1 R20.1)
GL_B: gate driver (U1.40), power MOSFET (D7.1 R21.1)
GL_C: gate driver (U1.35), power MOSFET (D8.1 R22.1)
HAL_A: rotor angle sensor (R28.2), main controller (U6.14)
HAL_B: rotor angle sensor (R29.2), main controller (U6.15)
HAL_C: rotor angle sensor (R30.2), main controller (U6.16)
INH_A: gate driver (U1.17), main controller (U6.43)
INH_B: gate driver (U1.19), main controller (U6.42)
INH_C: gate driver (U1.21), main controller (U6.41)
INL_A: gate driver (U1.18), main controller (U6.36)
INL_B: gate driver (U1.20), main controller (U6.35)
INL_C: gate driver (U1.22), main controller (U6.34)
M_OC: gate driver (U1.9), main controller (U6.39)
M_PWM: gate driver (U1.8), main controller (U6.40)
nFAULT: gate driver (U1.6), main controller (U6.22)
nOCTW: gate driver (U1.5), main controller (U6.21)
OC_ADJ: gate driver (J1.1), main controller (U6.20)
PV_SENSE: power MOSFET (C31.2 D2.1 R12.2 R13.1), main controller (U6.17)
SH_A: gate driver (C7.2 U1.46), power MOSFET (P3.X Q1.1 Q4.EXT R17.2)
SH_B: gate driver (C9.2 U1.41), power MOSFET (P4.X Q2.1 Q5.EXT R18.2)
SH_C: gate driver (C12.2 U1.36), power MOSFET (P5.X Q3.1 Q6.EXT R19.2)
SL_A: gate driver (U1.33 U1.44), power MOSFET (Q4.1 R23.1)
SL_B: gate driver (U1.31 U1.39), power MOSFET (Q5.1 R24.1)
SO1: gate driver (C17.1 R9.2), main controller (U6.26)
SO2: gate driver (C18.1 R10.2), main controller (U6.27)
SPI_CS: rotor angle sensor (U3.1), main controller (U6.50)
SPI_MISO: rotor angle sensor (U3.3), main controller (U6.56)
SPI_MOSI: rotor angle sensor (U3.4), main controller (U6.57)
SPI_SCK: rotor angle sensor (U3.2), main controller (U6.55)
